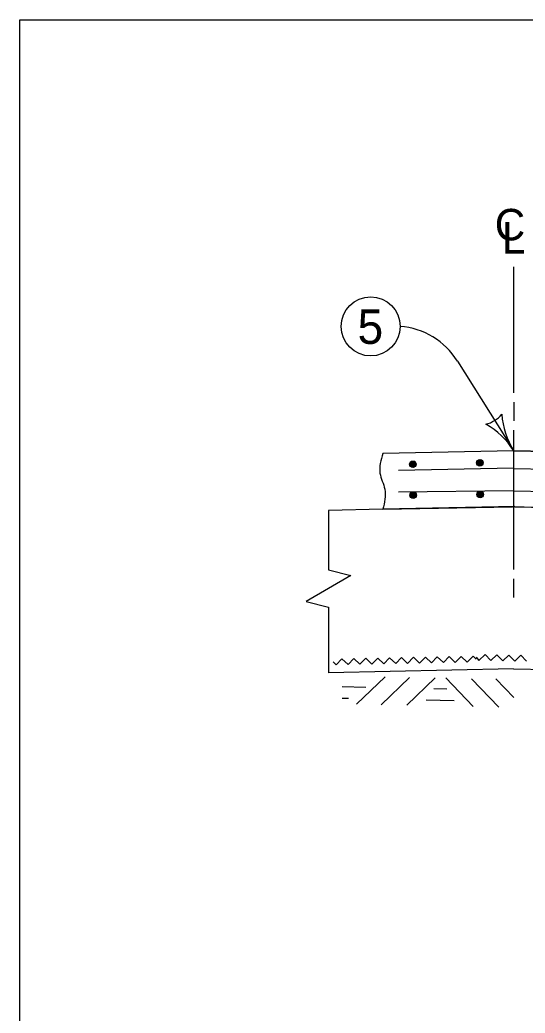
# Model space of a CAD drawing. Extents: x -2134934 to -2124557, y -2139046 to -2134021.
# Drawn here: x -2127734 to -2127478, y -2137540 to -2137036 of the extents above; entities that cross this region are included whole.
import ezdxf

# ---------------------------------------------------------------- set-up
doc = ezdxf.new("R2010")
doc.units = 0
for name, color, linetype in [('BridgeSuperStructureExisting', 7, 'Continuous'), ('dsnAlignmentStation', 7, 'Continuous'), ('dsnStdLabel', 7, 'Continuous')]:
    doc.layers.add(name, color=color, linetype=linetype)

msp = doc.modelspace()

# ---------------------------------------------------------------- linework, layer by layer
at = {"layer": 'BridgeSuperStructureExisting'}
for p, q in [((-2127512.26, -2137209.24), (-2127483.7, -2137254.79)), ((-2127483.71, -2137254.79), (-2127550.08, -2137256.13)), ((-2127483.71, -2137254.79), (-2127550.08, -2137256.13)), ((-2126773.45, -2137269.05), (-2127483.71, -2137254.79)), ((-2127483.71, -2137254.79), (-2126773.45, -2137269.05)), ((-2127483.74, -2137263.68), (-2127542.26, -2137264.86)), ((-2127483.71, -2137263.74), (-2126752.01, -2137278.43)), ((-2127483.74, -2137275.11), (-2127542.26, -2137275.74)), ((-2127550.08, -2137284.49), (-2127577.65, -2137285.04)), ((-2127577.65, -2137285.04), (-2127577.65, -2137315.3)), ((-2127483.14, -2137283.15), (-2127550.08, -2137284.49)), ((-2127550.08, -2137284.49), (-2127484.27, -2137283.17)), ((-2127484.27, -2137283.15), (-2127483.7, -2137283.16)), ((-2127484.27, -2137283.15), (-2126735.17, -2137298.18)), ((-2127483.7, -2137283.16), (-2127483.14, -2137283.15)), ((-2127483.14, -2137283.17), (-2126735.17, -2137298.18)), ((-2127577.65, -2137315.3), (-2127566.3, -2137318.14)), ((-2127566.3, -2137318.14), (-2127577.65, -2137324.75)), ((-2127577.65, -2137324.75), (-2127588.99, -2137331.37)), ((-2127588.99, -2137331.37), (-2127577.65, -2137334.21)), ((-2127577.65, -2137334.21), (-2127577.65, -2137367.47)), ((-2127483.71, -2137365.58), (-2127577.65, -2137367.47)), ((-2127483.71, -2137365.58), (-2126667.12, -2137381.97)), ((-2127549.02, -2137369.53), (-2127563.44, -2137383.38)), ((-2127536.58, -2137370), (-2127551, -2137383.86)), ((-2127523.57, -2137370.04), (-2127537.99, -2137383.89)), ((-2127518.16, -2137370.15), (-2127504.3, -2137384.57)), ((-2127505.15, -2137370.63), (-2127491.3, -2137385.06)), ((-2127492.7, -2137370.66), (-2127483.6, -2137380.13))]:
    msp.add_line(p, q, dxfattribs=at)
for points in [[(-2127483.71, -2137161.37), (-2127483.71, -2137225.33)], [(-2127483.7, -2137230.06), (-2127483.7, -2137239.52)], [(-2127483.71, -2137244.24), (-2127483.71, -2137315.14)], [(-2127533.36, -2137261.7), (-2127533.63, -2137261.15), (-2127533.93, -2137260.3), (-2127534.82, -2137260.16), (-2127535.59, -2137260.31), (-2127536.28, -2137260.9), (-2127536.17, -2137261.72), (-2127536.01, -2137262.59), (-2127535.31, -2137262.98), (-2127534.57, -2137263.02), (-2127533.63, -2137262.47), (-2127533.58, -2137261.83), (-2127533.84, -2137260.97), (-2127534.42, -2137260.28), (-2127535.25, -2137260.34), (-2127535.89, -2137260.92), (-2127535.93, -2137261.7), (-2127535.72, -2137262.57), (-2127535.23, -2137262.68), (-2127534.63, -2137262.83), (-2127533.93, -2137262.39), (-2127533.98, -2137261.76), (-2127534.12, -2137261.04), (-2127534.55, -2137260.53), (-2127535.26, -2137260.83), (-2127535.66, -2137261.39), (-2127535.65, -2137262.12), (-2127535.25, -2137262.29), (-2127534.8, -2137262.5), (-2127534.24, -2137262.12), (-2127534.14, -2137261.58), (-2127534.41, -2137261.11), (-2127534.95, -2137261.1), (-2127535.32, -2137261.37), (-2127535.43, -2137261.86), (-2127535.22, -2137262.09), (-2127534.92, -2137262.22), (-2127534.5, -2137261.95), (-2127534.43, -2137261.59), (-2127534.64, -2137261.27), (-2127534.93, -2137261.34), (-2127535.11, -2137261.6), (-2127535.08, -2137261.94), (-2127534.84, -2137261.92), (-2127534.72, -2137261.62)], [(-2127499.32, -2137260.99), (-2127499.6, -2137260.44), (-2127499.9, -2137259.59), (-2127500.79, -2137259.46), (-2127501.55, -2137259.61), (-2127502.25, -2137260.19), (-2127502.14, -2137261.01), (-2127501.98, -2137261.88), (-2127501.27, -2137262.27), (-2127500.54, -2137262.32), (-2127499.6, -2137261.76), (-2127499.55, -2137261.13), (-2127499.8, -2137260.26), (-2127500.39, -2137259.58), (-2127501.21, -2137259.63), (-2127501.86, -2137260.21), (-2127501.89, -2137261), (-2127501.69, -2137261.86), (-2127501.2, -2137261.97), (-2127500.6, -2137262.13), (-2127499.9, -2137261.68), (-2127499.94, -2137261.05), (-2127500.09, -2137260.33), (-2127500.51, -2137259.83), (-2127501.23, -2137260.12), (-2127501.63, -2137260.68), (-2127501.62, -2137261.42), (-2127501.22, -2137261.58), (-2127500.77, -2137261.8), (-2127500.21, -2137261.41), (-2127500.1, -2137260.87), (-2127500.38, -2137260.4), (-2127500.92, -2137260.39), (-2127501.29, -2137260.66), (-2127501.4, -2137261.16), (-2127501.19, -2137261.39), (-2127500.89, -2137261.51), (-2127500.46, -2137261.24), (-2127500.4, -2137260.89), (-2127500.61, -2137260.56), (-2127500.9, -2137260.63), (-2127501.08, -2137260.89), (-2127501.05, -2137261.23), (-2127500.81, -2137261.21), (-2127500.69, -2137260.91)], [(-2127533.19, -2137277.39), (-2127533.45, -2137276.84), (-2127533.75, -2137275.98), (-2127534.64, -2137275.84), (-2127535.41, -2137275.98), (-2127536.1, -2137276.56), (-2127536, -2137277.39), (-2127535.85, -2137278.25), (-2127535.14, -2137278.65), (-2127534.41, -2137278.7), (-2127533.47, -2137278.16), (-2127533.41, -2137277.52), (-2127533.66, -2137276.66), (-2127534.24, -2137275.96), (-2127535.06, -2137276.01), (-2127535.71, -2137276.59), (-2127535.76, -2137277.37), (-2127535.56, -2137278.24), (-2127535.07, -2137278.35), (-2127534.47, -2137278.51), (-2127533.77, -2137278.08), (-2127533.81, -2137277.45), (-2127533.95, -2137276.73), (-2127534.37, -2137276.21), (-2127535.08, -2137276.5), (-2127535.49, -2137277.06), (-2127535.49, -2137277.79), (-2127535.09, -2137277.96), (-2127534.64, -2137278.18), (-2127534.08, -2137277.81), (-2127533.96, -2137277.26), (-2127534.23, -2137276.79), (-2127534.77, -2137276.77), (-2127535.14, -2137277.04), (-2127535.26, -2137277.54), (-2127535.05, -2137277.77), (-2127534.76, -2137277.89), (-2127534.33, -2137277.63), (-2127534.26, -2137277.28), (-2127534.47, -2137276.95), (-2127534.76, -2137277.02), (-2127534.93, -2137277.27), (-2127534.92, -2137277.61), (-2127534.67, -2137277.6), (-2127534.55, -2137277.3)], [(-2127499.15, -2137277.03), (-2127499.42, -2137276.48), (-2127499.71, -2137275.62), (-2127500.6, -2137275.47), (-2127501.37, -2137275.62), (-2127502.06, -2137276.2), (-2127501.96, -2137277.02), (-2127501.81, -2137277.89), (-2127501.11, -2137278.29), (-2127500.38, -2137278.34), (-2127499.44, -2137277.8), (-2127499.37, -2137277.16), (-2127499.62, -2137276.3), (-2127500.2, -2137275.6), (-2127501.02, -2137275.65), (-2127501.67, -2137276.22), (-2127501.72, -2137277.01), (-2127501.52, -2137277.87), (-2127501.03, -2137277.99), (-2127500.44, -2137278.15), (-2127499.73, -2137277.72), (-2127499.77, -2137277.08), (-2127499.91, -2137276.36), (-2127500.33, -2137275.85), (-2127501.04, -2137276.14), (-2127501.45, -2137276.7), (-2127501.46, -2137277.43), (-2127501.05, -2137277.6), (-2127500.6, -2137277.81), (-2127500.04, -2137277.44), (-2127499.92, -2137276.9), (-2127500.2, -2137276.43), (-2127500.73, -2137276.41), (-2127501.11, -2137276.68), (-2127501.23, -2137277.17), (-2127501.01, -2137277.4), (-2127500.72, -2137277.53), (-2127500.29, -2137277.26), (-2127500.22, -2137276.92), (-2127500.43, -2137276.59), (-2127500.72, -2137276.65), (-2127500.9, -2137276.91), (-2127500.88, -2137277.25), (-2127500.64, -2137277.24), (-2127500.51, -2137276.93)], [(-2127484.27, -2137283.17), (-2127484.27, -2137283.15)], [(-2127483.14, -2137283.15), (-2127483.14, -2137283.17)], [(-2127483.71, -2137319.86), (-2127483.71, -2137329.32)], [(-2127575.38, -2137361.99), (-2127573.84, -2137363.47), (-2127570.87, -2137360.38), (-2127567.79, -2137363.35), (-2127564.83, -2137360.26), (-2127561.74, -2137363.22), (-2127558.78, -2137360.14), (-2127555.69, -2137363.1), (-2127552.73, -2137360.02), (-2127549.64, -2137362.98), (-2127546.68, -2137359.9), (-2127543.59, -2137362.86), (-2127540.63, -2137359.78), (-2127537.55, -2137362.74), (-2127534.58, -2137359.65), (-2127531.5, -2137362.62), (-2127528.53, -2137359.53), (-2127525.45, -2137362.5), (-2127522.48, -2137359.41), (-2127519.4, -2137362.37), (-2127516.44, -2137359.29), (-2127513.35, -2137362.25), (-2127510.39, -2137359.17), (-2127507.3, -2137362.13), (-2127504.34, -2137359.05), (-2127502.79, -2137360.53)], [(-2127502.79, -2137359.67), (-2127501.31, -2137361.21), (-2127498.23, -2137358.25), (-2127495.26, -2137361.34), (-2127492.18, -2137358.38), (-2127489.22, -2137361.46), (-2127486.13, -2137358.5), (-2127483.17, -2137361.58), (-2127480.08, -2137358.61), (-2127477.12, -2137361.7)], [(-2127570.74, -2137374.57), (-2127558.71, -2137374.81)], [(-2127524.24, -2137375.52), (-2127517.7, -2137375.66)], [(-2127570.85, -2137380.37), (-2127567.59, -2137380.43)], [(-2127528.18, -2137381.3), (-2127513.99, -2137381.59)]]:
    msp.add_lwpolyline(points, dxfattribs=at)
for centre, radius in [((-2127556.3, -2137191.64), 15), ((-2127534.87, -2137261.63), 1.65), ((-2127500.84, -2137260.93), 1.65), ((-2127534.7, -2137277.31), 1.65), ((-2127500.67, -2137276.95), 1.65)]:
    msp.add_circle(centre, radius, dxfattribs=at)
for centre, radius, start, end in [((-2127544.3, -2137229.33), 37.81, 32.09, 85.4518), ((-2127501.6, -2137226.25), 15.52, 284.3569, 319.8236), ((-2127501.6, -2137226.25), 15.52, 284.3569, 319.8236), ((-2127449.67, -2137233.45), 40.18, 184.0178, 212.0903), ((-2127449.67, -2137233.45), 40.18, 184.0178, 212.0903), ((-2127517.74, -2137276.14), 40.18, 32.0903, 60.1628), ((-2127517.74, -2137276.14), 40.18, 32.0903, 60.1628)]:
    msp.add_arc(centre, radius, start, end, dxfattribs=at)
msp.add_spline([(-2127550.08, -2137256.13), (-2127551.6, -2137266.21), (-2127549.14, -2137274.34), (-2127550.08, -2137284.49)], degree=3, dxfattribs=at)
msp.add_spline([(-2127550.08, -2137256.13), (-2127551.6, -2137266.21), (-2127549.14, -2137274.34), (-2127550.08, -2137284.49)], degree=3, dxfattribs=at)
at = {"layer": 'dsnAlignmentStation'}
msp.add_lwpolyline([(-2127734.44, -2137035.95), (-2124599.45, -2137035.95), (-2124599.45, -2139045.94), (-2127734.44, -2139045.94)], close=True, dxfattribs=at)
at = {"layer": 'dsnStdLabel'}
msp.add_line((-2126752.19, -2137288.89), (-2127483.74, -2137275.34), dxfattribs=at)

# ---------------------------------------------------------------- texts
for s, height, p in [('C', 16, (-2127493.3, -2137147.94)), ('L', 16, (-2127489.71, -2137154.64)), ('5', 17.5, (-2127562.96, -2137200.5))]:
    msp.add_text(s, height=height, dxfattribs=at).set_placement(p)

doc.saveas('drawing.dxf')
